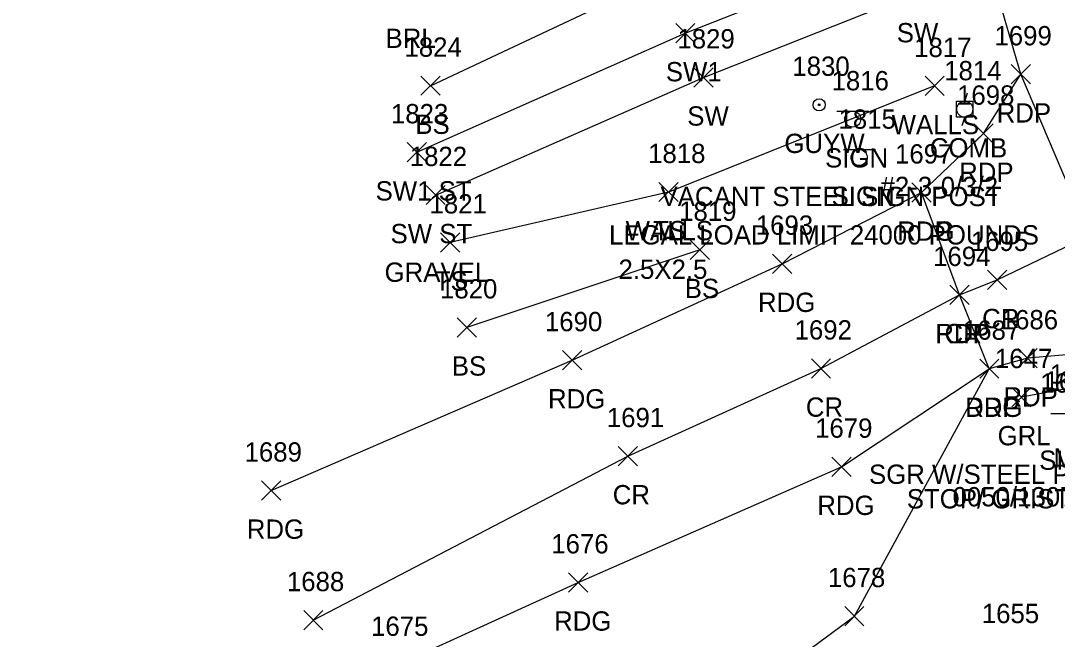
# Model space of a CAD drawing. Extents: x 1620157 to 1620595, y 115111 to 117885.
# Drawn here: x 1620193.4 to 1620300.9, y 115437.5 to 115501.6 of the extents above; entities that cross this region are included whole.
import ezdxf

# ---------------------------------------------------------------- set-up
doc = ezdxf.new("R2010")
doc.units = 0
for name, color, linetype in [('L_A', 7, 'Continuous'), ('L_C', 7, 'Continuous'), ('L_I', 7, 'Continuous'), ('L_TIC', 7, 'Continuous'), ('LELB', 7, 'Continuous'), ('LWS', 7, 'Continuous'), ('P_A', 7, 'Continuous'), ('P_I', 7, 'Continuous'), ('P_TIC', 7, 'Continuous'), ('PET', 7, 'Continuous'), ('PEU', 7, 'Continuous'), ('PRC', 7, 'Continuous'), ('R_A', 7, 'Continuous'), ('R_C', 7, 'Continuous'), ('R_I', 7, 'Continuous'), ('R_TIC', 7, 'Continuous'), ('RDG', 7, 'Continuous'), ('RGR', 7, 'Continuous'), ('RSW', 7, 'Continuous'), ('S_A', 7, 'Continuous'), ('S_C', 7, 'Continuous'), ('S_I', 7, 'Continuous'), ('SSGN', 7, 'Continuous'), ('U_A', 7, 'Continuous'), ('U_C', 7, 'Continuous'), ('U_I', 7, 'Continuous'), ('UP', 7, 'Continuous'), ('UPGW', 7, 'Continuous')]:
    doc.layers.add(name, color=color, linetype=linetype)

msp = doc.modelspace()

# ---------------------------------------------------------------- linework, layer by layer
at = {"layer": 'L_TIC'}
for points in [[(1620234.85, 115493.91), (1620236.85, 115495.91)], [(1620236.85, 115493.91), (1620234.85, 115495.91)], [(1620287.15, 115493.88), (1620289.15, 115495.88)], [(1620289.15, 115493.88), (1620287.15, 115495.88)], [(1620259.55, 115482.89), (1620261.55, 115484.89)], [(1620261.55, 115482.89), (1620259.55, 115484.89)], [(1620259.55, 115482.89), (1620261.55, 115484.89)], [(1620261.55, 115482.89), (1620259.55, 115484.89)], [(1620236.89, 115477.67), (1620238.89, 115479.67)], [(1620238.89, 115477.67), (1620236.89, 115479.67)], [(1620262.79, 115476.9), (1620264.79, 115478.9)], [(1620264.79, 115476.9), (1620262.79, 115478.9)], [(1620238.63, 115468.86), (1620240.63, 115470.86)], [(1620240.63, 115468.86), (1620238.63, 115470.86)]]:
    msp.add_lwpolyline(points, dxfattribs=at)
at = {"layer": 'LELB'}
for points in [[(1620235.85, 115494.91), (1620261.29, 115506.88)], [(1620260.55, 115483.89), (1620237.89, 115478.67)], [(1620263.79, 115477.9), (1620239.63, 115469.86)]]:
    msp.add_lwpolyline(points, dxfattribs=at)
at = {"layer": 'LWS'}
msp.add_lwpolyline([(1620288.15, 115494.88), (1620260.55, 115483.89)], dxfattribs=at)
at = {"layer": 'P_TIC'}
for points in [[(1620296.09, 115495.09), (1620298.09, 115497.09)], [(1620298.09, 115495.09), (1620296.09, 115497.09)], [(1620296.09, 115495.09), (1620298.09, 115497.09)], [(1620298.09, 115495.09), (1620296.09, 115497.09)], [(1620292.21, 115488.94), (1620294.21, 115490.94)], [(1620294.21, 115488.94), (1620292.21, 115490.94)], [(1620285.78, 115482.84), (1620287.78, 115484.84)], [(1620287.78, 115482.84), (1620285.78, 115484.84)], [(1620285.78, 115482.84), (1620287.78, 115484.84)], [(1620287.78, 115482.84), (1620285.78, 115484.84)], [(1620271.34, 115475.46), (1620273.34, 115477.46)], [(1620273.34, 115475.46), (1620271.34, 115477.46)], [(1620293.64, 115473.78), (1620295.64, 115475.78)], [(1620295.64, 115473.78), (1620293.64, 115475.78)], [(1620289.73, 115472.22), (1620291.73, 115474.22)], [(1620291.73, 115472.22), (1620289.73, 115474.22)], [(1620289.73, 115472.22), (1620291.73, 115474.22)], [(1620291.73, 115472.22), (1620289.73, 115474.22)], [(1620249.56, 115465.46), (1620251.56, 115467.46)], [(1620251.56, 115465.46), (1620249.56, 115467.46)], [(1620296.79, 115465.66), (1620298.79, 115467.66)], [(1620298.79, 115465.66), (1620296.79, 115467.66)], [(1620275.36, 115464.6), (1620277.36, 115466.6)], [(1620277.36, 115464.6), (1620275.36, 115466.6)], [(1620292.82, 115464.58), (1620294.82, 115466.58)], [(1620294.82, 115464.58), (1620292.82, 115466.58)], [(1620292.82, 115464.58), (1620294.82, 115466.58)], [(1620294.82, 115464.58), (1620292.82, 115466.58)], [(1620255.33, 115455.52), (1620257.33, 115457.52)], [(1620257.33, 115455.52), (1620255.33, 115457.52)], [(1620277.49, 115454.42), (1620279.49, 115456.42)], [(1620279.49, 115454.42), (1620277.49, 115456.42)], [(1620218.33, 115451.95), (1620220.33, 115453.95)], [(1620220.33, 115451.95), (1620218.33, 115453.95)], [(1620250.19, 115442.43), (1620252.19, 115444.43)], [(1620252.19, 115442.43), (1620250.19, 115444.43)], [(1620222.71, 115438.52), (1620224.71, 115440.52)], [(1620224.71, 115438.52), (1620222.71, 115440.52)]]:
    msp.add_lwpolyline(points, dxfattribs=at)
at = {"layer": 'PET'}
for points in [[(1620320.14, 115439.39), (1620314.87, 115455.06), (1620309.06, 115464.39), (1620304.22, 115479.4), (1620297.09, 115496.09), (1620293.95, 115506.93), (1620292.02, 115512.47), (1620283.67, 115536.02), (1620274.58, 115564.81), (1620268.48, 115584.52), (1620253.11, 115635.23), (1620250.12, 115643.88), (1620242.65, 115668.01), (1620237.66, 115684.19), (1620235.08, 115693.76), (1620231.19, 115707.41), (1620225.41, 115727.43), (1620211.93, 115771.95), (1620203.83, 115799.04), (1620193.37, 115837.22)], [(1620309.06, 115464.39), (1620303.44, 115467.14), (1620297.79, 115466.66), (1620293.82, 115465.58), (1620290.73, 115473.22), (1620286.78, 115483.84), (1620293.21, 115489.94), (1620297.09, 115496.09)]]:
    msp.add_lwpolyline(points, dxfattribs=at)
at = {"layer": 'PEU'}
for points in [[(1620219.33, 115452.95), (1620250.56, 115466.46), (1620272.34, 115476.46), (1620286.78, 115483.84)], [(1620201.7, 115419.53), (1620232.44, 115434.89), (1620251.19, 115443.43), (1620278.49, 115455.42), (1620293.82, 115465.58)]]:
    msp.add_lwpolyline(points, dxfattribs=at)
at = {"layer": 'PRC'}
msp.add_lwpolyline([(1620223.71, 115439.52), (1620256.33, 115456.52), (1620276.36, 115465.6), (1620290.73, 115473.22), (1620294.64, 115474.78), (1620304.22, 115479.4)], dxfattribs=at)
at = {"layer": 'R_TIC'}
for points in [[(1620261.29, 115499.36), (1620263.29, 115501.36)], [(1620263.29, 115499.36), (1620261.29, 115501.36)], [(1620263.17, 115494.77), (1620265.17, 115496.77)], [(1620265.17, 115494.77), (1620263.17, 115496.77)], [(1620233.45, 115487.01), (1620235.45, 115489.01)], [(1620235.45, 115487.01), (1620233.45, 115489.01)], [(1620235.4, 115482.58), (1620237.4, 115484.58)], [(1620237.4, 115482.58), (1620235.4, 115484.58)], [(1620292.82, 115464.58), (1620294.82, 115466.58)], [(1620294.82, 115464.58), (1620292.82, 115466.58)], [(1620296.14, 115461.64), (1620298.14, 115463.64)], [(1620298.14, 115461.64), (1620296.14, 115463.64)], [(1620278.82, 115438.94), (1620280.82, 115440.94)], [(1620280.82, 115438.94), (1620278.82, 115440.94)]]:
    msp.add_lwpolyline(points, dxfattribs=at)
at = {"layer": 'RDG'}
msp.add_lwpolyline([(1620201.7, 115419.53), (1620220.41, 115407.46), (1620239.44, 115415.84), (1620256.84, 115422.98), (1620279.82, 115439.94), (1620293.82, 115465.58)], dxfattribs=at)
at = {"layer": 'RGR'}
msp.add_lwpolyline([(1620319.47, 115439.94), (1620315.8, 115450.15), (1620311.64, 115458.04), (1620307.61, 115462.52), (1620304.03, 115463.92), (1620297.14, 115462.64)], dxfattribs=at)
at = {"layer": 'RSW'}
for points in [[(1620234.45, 115488.01), (1620262.29, 115500.36), (1620284.61, 115509.15), (1620292.02, 115512.47)], [(1620236.4, 115483.58), (1620264.17, 115495.77), (1620285.91, 115504.4), (1620293.95, 115506.93)]]:
    msp.add_lwpolyline(points, dxfattribs=at)
at = {"layer": 'SSGN'}
for p, q in [((1620278.01, 115492.28), (1620281.34, 115492.28)), ((1620279.66, 115491.45), (1620279.66, 115491.45)), ((1620278.68, 115488.3), (1620282.01, 115488.3)), ((1620280.32, 115487.47), (1620280.32, 115487.47)), ((1620300.21, 115460.95), (1620303.54, 115460.95))]:
    msp.add_line(p, q, dxfattribs=at)
for centre in [(1620279.66, 115491.45), (1620280.32, 115487.47)]:
    msp.add_circle(centre, 0.833, dxfattribs=at)
at = {"layer": 'UP'}
for p, q in [((1620291.52, 115494.14), (1620291.27, 115493.3)), ((1620290.43, 115491.64), (1620290.43, 115493.3)), ((1620290.43, 115493.3), (1620292.1, 115493.3)), ((1620292.1, 115493.3), (1620292.1, 115491.64)), ((1620291.27, 115492.47), (1620291.27, 115492.47)), ((1620292.1, 115491.64), (1620290.43, 115491.64)), ((1620291.02, 115490.8), (1620291.27, 115491.64))]:
    msp.add_line(p, q, dxfattribs=at)
msp.add_circle((1620291.27, 115492.47), 0.833, dxfattribs=at)
at = {"layer": 'UPGW'}
for radius in [0.625, 0.0833]:
    msp.add_circle((1620276.17, 115492.93), radius, dxfattribs=at)

# ---------------------------------------------------------------- texts
at = {"layer": 'L_A'}
for s, p in [('BRL', (1620231.2, 115498.82)), ('BS', (1620234.29, 115489.91)), ('WALLS', (1620283.69, 115489.88)), ('WALLS', (1620256.1, 115478.89)), ('TS', (1620258.96, 115478.89)), ('TS', (1620236.3, 115473.67)), ('BS', (1620262.23, 115472.9)), ('BS', (1620238.07, 115464.86))]:
    msp.add_text(s, height=2, dxfattribs=at).set_placement(p)
at = {"layer": 'L_C'}
msp.add_text('2.5X2.5', height=2, dxfattribs=at).set_placement((1620255.36, 115474.89))
at = {"layer": 'L_I'}
for s, p in [('1824', (1620233.16, 115497.91)), ('1817', (1620286.02, 115497.88)), ('1818', (1620258.43, 115486.89)), ('1818', (1620258.43, 115486.89)), ('1821', (1620235.76, 115481.67)), ('1819', (1620261.65, 115480.9)), ('1820', (1620236.85, 115472.86)), ('1650', (1620300.08, 115464.02)), ('1655', (1620293.04, 115439.21))]:
    msp.add_text(s, height=2, dxfattribs=at).set_placement(p)
at = {"layer": 'P_A'}
for s, p in [('RDP', (1620294.58, 115491.09)), ('RDP', (1620294.58, 115491.09)), ('RDP', (1620290.69, 115484.94)), ('RDG', (1620284.27, 115478.84)), ('RDP', (1620284.27, 115478.84)), ('RDG', (1620269.83, 115471.46)), ('CR', (1620293.07, 115469.78)), ('RDP', (1620288.22, 115468.22)), ('CR', (1620289.17, 115468.22)), ('RDG', (1620248.05, 115461.46)), ('RDP', (1620295.28, 115461.66)), ('CR', (1620274.79, 115460.6)), ('RDG', (1620291.31, 115460.58)), ('RDP', (1620291.31, 115460.58)), ('CR', (1620254.76, 115451.52)), ('RDG', (1620275.98, 115450.42)), ('RDG', (1620216.81, 115447.95)), ('RDG', (1620248.68, 115438.43))]:
    msp.add_text(s, height=2, dxfattribs=at).set_placement(p)
at = {"layer": 'P_I'}
for s, p in [('1699', (1620294.35, 115499.09)), ('1699', (1620294.35, 115499.09)), ('1698', (1620290.47, 115492.94)), ('1697', (1620284.04, 115486.84)), ('1697', (1620284.04, 115486.84)), ('1693', (1620269.6, 115479.46)), ('1695', (1620291.9, 115477.78)), ('1694', (1620287.99, 115476.22)), ('1694', (1620287.99, 115476.22)), ('1690', (1620247.73, 115469.46)), ('1686', (1620295, 115469.66)), ('1692', (1620273.62, 115468.6)), ('1687', (1620291.08, 115468.58)), ('1687', (1620291.08, 115468.58)), ('1691', (1620254.15, 115459.52)), ('1679', (1620275.75, 115458.42)), ('1689', (1620216.58, 115455.95)), ('1676', (1620248.39, 115446.43)), ('1688', (1620220.97, 115442.52)), ('1675', (1620229.7, 115437.89))]:
    msp.add_text(s, height=2, dxfattribs=at).set_placement(p)
at = {"layer": 'R_A'}
for s, p in [('SW', (1620284.22, 115499.4)), ('SW1', (1620260.27, 115495.36)), ('SW', (1620262.49, 115490.77)), ('SW1 ST', (1620230.17, 115483.01)), ('SW ST', (1620231.72, 115478.58)), ('DRG', (1620291.31, 115460.58)), ('GRL', (1620294.68, 115457.64))]:
    msp.add_text(s, height=2, dxfattribs=at).set_placement(p)
at = {"layer": 'R_C'}
for s, p in [('GRAVEL', (1620231.1, 115474.58)), ('SGR W/STEEL POSTS', (1620281.34, 115453.64))]:
    msp.add_text(s, height=2, dxfattribs=at).set_placement(p)
at = {"layer": 'R_I'}
for s, p in [('1829', (1620261.47, 115498.77)), ('1823', (1620231.76, 115491.01)), ('1822', (1620233.71, 115486.58)), ('1687', (1620291.08, 115468.58)), ('1647', (1620294.4, 115465.64)), ('1678', (1620277.08, 115442.94))]:
    msp.add_text(s, height=2, dxfattribs=at).set_placement(p)
at = {"layer": 'S_A'}
for s, p in [('SIGN', (1620276.79, 115486.43)), ('SIGN', (1620277.46, 115482.45)), ('SIGN', (1620298.99, 115455.1)), ('MM', (1620300.47, 115455.31))]:
    msp.add_text(s, height=2, dxfattribs=at).set_placement(p)
at = {"layer": 'S_C'}
for s, p in [('VACANT STEEL SIGN POST', (1620259.72, 115482.43)), ('LEGAL LOAD LIMIT 24000 POUNDS', (1620254.38, 115478.45)), ('STOP/ GRIST MILL RD', (1620285.26, 115451.1)), ('0050/1307/0622', (1620290.01, 115451.31))]:
    msp.add_text(s, height=2, dxfattribs=at).set_placement(p)
at = {"layer": 'S_I'}
for s, p in [('1816', (1620277.46, 115494.43)), ('1815', (1620278.18, 115490.45)), ('1648', (1620299.09, 115463.1)), ('1649', (1620299.53, 115463.31))]:
    msp.add_text(s, height=2, dxfattribs=at).set_placement(p)
at = {"layer": 'U_A'}
for s, p in [('GUYW', (1620272.57, 115487.93)), ('COMB', (1620287.65, 115487.47))]:
    msp.add_text(s, height=2, dxfattribs=at).set_placement(p)
at = {"layer": 'U_C'}
msp.add_text('#2-3-0/3/2', height=2, dxfattribs=at).set_placement((1620282.54, 115483.47))
at = {"layer": 'U_I'}
for s, p in [('1830', (1620273.39, 115495.93)), ('1814', (1620289.14, 115495.47))]:
    msp.add_text(s, height=2, dxfattribs=at).set_placement(p)

doc.saveas('drawing.dxf')
